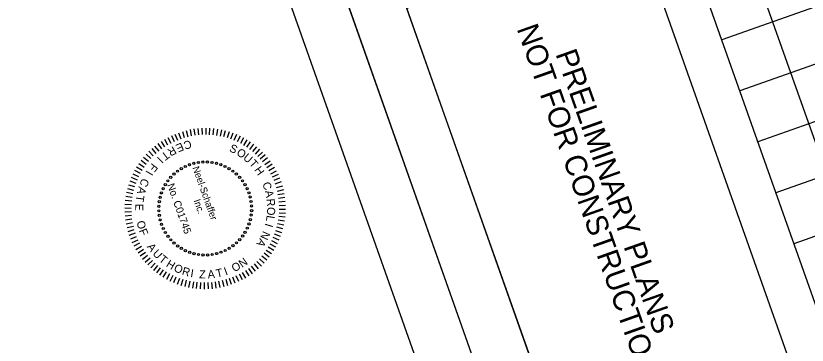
# Model space of a CAD drawing. Extents: x 2002686 to 2004357, y 1138437 to 1140501.
# Drawn here: x 2002880 to 2003246.2, y 1139042.8 to 1139195.1 of the extents above; entities that cross this region are included whole.
import ezdxf

# ---------------------------------------------------------------- set-up
doc = ezdxf.new("R2010")
doc.units = 0
for name, color, linetype in [('RD_SHT_Bndy', 7, 'Continuous'), ('RD_SHT_IplotShp', 7, 'Continuous'), ('RD_SHT_Misc1', 7, 'Continuous'), ('RD_SHT_MjGrid', 7, 'Continuous'), ('RD_SHT_MnGrid', 7, 'Continuous'), ('RD_SHT_TX', 7, 'Continuous')]:
    doc.layers.add(name, color=color, linetype=linetype)

msp = doc.modelspace()

# ---------------------------------------------------------------- linework, layer by layer
at = {"layer": 'RD_SHT_Bndy'}
for p, q in [((2003296.55, 1138457.43), (2002709.57, 1140116.66)), ((2003272.98, 1138449.09), (2002686, 1140108.32)), ((2002760.69, 1140047.13), (2003319.32, 1138468.03))]:
    msp.add_line(p, q, dxfattribs=at)
msp.add_lwpolyline([(2003166.91, 1139236.17), (2003241.95, 1139024.06), (2003135.89, 1138986.54), (2003060.85, 1139198.65)], close=True, dxfattribs=at)
at = {"layer": 'RD_SHT_IplotShp'}
msp.add_lwpolyline([(2003740.39, 1140501.06), (2004340.71, 1138804.11), (2003303.69, 1138437.25), (2002703.37, 1140134.19)], close=True, dxfattribs=at)
at = {"layer": 'RD_SHT_Misc1'}
for p, q in [((2002966.05, 1139143.11), (2002966.18, 1139140.14)), ((2002967.87, 1139143.14), (2002967.85, 1139140.17)), ((2002951.96, 1139139.68), (2002953.22, 1139136.99)), ((2002953.63, 1139140.4), (2002954.75, 1139137.66)), ((2002955.34, 1139141.05), (2002956.32, 1139138.25)), ((2002957.07, 1139141.61), (2002957.92, 1139138.77)), ((2002958.83, 1139142.08), (2002959.54, 1139139.2)), ((2002960.62, 1139142.47), (2002961.18, 1139139.56)), ((2002962.42, 1139142.77), (2002962.84, 1139139.84)), ((2002964.23, 1139142.98), (2002964.5, 1139140.03)), ((2002969.69, 1139143.08), (2002969.53, 1139140.12)), ((2002971.51, 1139142.94), (2002971.2, 1139139.99)), ((2002973.32, 1139142.7), (2002972.87, 1139139.77)), ((2002975.11, 1139142.38), (2002974.52, 1139139.47)), ((2002976.89, 1139141.97), (2002976.16, 1139139.1)), ((2002978.64, 1139141.47), (2002977.77, 1139138.64)), ((2002980.37, 1139140.89), (2002979.36, 1139138.1)), ((2002982.07, 1139140.22), (2002980.92, 1139137.49)), ((2002983.73, 1139139.48), (2002982.45, 1139136.8)), ((2002945.69, 1139135.98), (2002947.44, 1139133.58)), ((2002947.19, 1139137.01), (2002948.82, 1139134.54)), ((2002948.73, 1139137.98), (2002950.25, 1139135.43)), ((2002950.33, 1139138.87), (2002951.71, 1139136.24)), ((2002985.36, 1139138.65), (2002983.95, 1139136.04)), ((2002986.94, 1139137.74), (2002985.4, 1139135.2)), ((2002988.47, 1139136.75), (2002986.81, 1139134.29)), ((2002941.53, 1139132.43), (2002943.61, 1139130.32)), ((2002942.86, 1139133.68), (2002944.84, 1139131.47)), ((2002944.24, 1139134.86), (2002946.11, 1139132.56)), ((2002989.96, 1139135.7), (2002988.18, 1139133.32)), ((2002991.39, 1139134.57), (2002989.5, 1139132.28)), ((2002992.76, 1139133.37), (2002990.76, 1139131.18)), ((2002939.06, 1139129.75), (2002941.34, 1139127.86)), ((2002940.26, 1139131.12), (2002942.45, 1139129.12)), ((2002994.07, 1139132.1), (2002991.97, 1139130.01)), ((2002995.32, 1139130.77), (2002993.12, 1139128.79)), ((2002996.51, 1139129.39), (2002994.21, 1139127.51)), ((2002935.88, 1139125.3), (2002938.42, 1139123.76)), ((2002936.87, 1139126.84), (2002939.32, 1139125.18)), ((2002937.93, 1139128.32), (2002940.3, 1139126.54)), ((2002997.62, 1139127.94), (2002995.23, 1139126.18)), ((2002998.66, 1139126.45), (2002996.19, 1139124.81)), ((2002999.63, 1139124.9), (2002997.08, 1139123.39)), ((2002934.14, 1139122.1), (2002936.81, 1139120.82)), ((2002934.97, 1139123.72), (2002937.58, 1139122.31)), ((2003000.52, 1139123.31), (2002997.9, 1139121.92)), ((2003001.33, 1139121.68), (2002998.65, 1139120.42)), ((2002932.72, 1139118.74), (2002935.5, 1139117.73)), ((2002933.39, 1139120.44), (2002936.12, 1139119.29)), ((2003002.06, 1139120.01), (2002999.32, 1139118.88)), ((2003002.71, 1139118.3), (2002999.91, 1139117.31)), ((2002931.63, 1139115.26), (2002934.51, 1139114.52)), ((2002932.13, 1139117.02), (2002934.97, 1139116.14)), ((2003003.33, 1139116.37), (2003000.48, 1139115.53)), ((2003003.8, 1139114.6), (2003000.91, 1139113.91)), ((2002930.89, 1139111.69), (2002933.83, 1139111.24)), ((2002931.22, 1139113.49), (2002934.13, 1139112.89)), ((2003004.18, 1139112.82), (2003001.26, 1139112.27)), ((2003004.47, 1139111.02), (2003001.53, 1139110.61)), ((2002930.51, 1139108.07), (2002933.47, 1139107.9)), ((2002930.66, 1139109.88), (2002933.61, 1139109.58)), ((2003004.68, 1139109.21), (2003001.72, 1139108.94)), ((2003004.79, 1139107.39), (2003001.83, 1139107.27)), ((2002930.45, 1139106.24), (2002933.42, 1139106.23)), ((2002930.48, 1139104.42), (2002933.45, 1139104.55)), ((2002930.6, 1139102.6), (2002933.56, 1139102.87)), ((2003004.75, 1139103.74), (2003001.79, 1139103.92)), ((2003004.82, 1139105.57), (2003001.85, 1139105.59)), ((2002930.81, 1139100.79), (2002933.75, 1139101.21)), ((2002931.11, 1139098.99), (2002934.02, 1139099.55)), ((2003004.36, 1139100.12), (2003001.43, 1139100.58)), ((2003004.6, 1139101.93), (2003001.65, 1139102.24)), ((2002931.49, 1139097.21), (2002934.38, 1139097.91)), ((2002931.97, 1139095.45), (2002934.81, 1139096.29)), ((2003003.1, 1139094.8), (2003000.27, 1139095.68)), ((2003003.61, 1139096.55), (2003000.74, 1139097.3)), ((2003004.03, 1139098.33), (2003001.12, 1139098.93)), ((2002932.52, 1139093.71), (2002935.32, 1139094.69)), ((2002933.17, 1139092), (2002935.91, 1139093.12)), ((2003001.84, 1139091.38), (2002999.11, 1139092.54)), ((2003002.52, 1139093.07), (2002999.73, 1139094.1)), ((2002933.89, 1139090.33), (2002936.58, 1139091.58)), ((2002934.7, 1139088.7), (2002937.32, 1139090.08)), ((2002935.58, 1139087.1), (2002938.14, 1139088.61)), ((2003000.25, 1139088.1), (2002997.64, 1139089.52)), ((2003001.09, 1139089.72), (2002998.41, 1139091.01)), ((2002936.55, 1139085.55), (2002939.02, 1139087.19)), ((2002937.58, 1139084.05), (2002939.98, 1139085.81)), ((2002997.28, 1139083.51), (2002994.91, 1139085.3)), ((2002998.34, 1139084.99), (2002995.89, 1139086.66)), ((2002999.33, 1139086.52), (2002996.8, 1139088.07)), ((2002938.69, 1139082.61), (2002941, 1139084.47)), ((2002939.87, 1139081.22), (2002942.09, 1139083.19)), ((2002941.12, 1139079.89), (2002943.23, 1139081.97)), ((2002993.67, 1139079.41), (2002991.59, 1139081.52)), ((2002994.94, 1139080.71), (2002992.76, 1139082.73)), ((2002996.14, 1139082.08), (2002993.87, 1139083.98)), ((2002942.43, 1139078.62), (2002944.44, 1139080.8)), ((2002943.8, 1139077.41), (2002945.7, 1139079.69)), ((2002945.23, 1139076.28), (2002947.01, 1139078.65)), ((2002946.71, 1139075.22), (2002948.38, 1139077.67)), ((2002987.99, 1139074.84), (2002986.37, 1139077.32)), ((2002989.49, 1139075.88), (2002987.75, 1139078.27)), ((2002990.94, 1139076.98), (2002989.08, 1139079.29)), ((2002992.34, 1139078.16), (2002990.36, 1139080.38)), ((2002948.24, 1139074.23), (2002949.79, 1139076.76)), ((2002949.82, 1139073.32), (2002951.24, 1139075.92)), ((2002951.44, 1139072.48), (2002952.73, 1139075.16)), ((2002953.1, 1139071.73), (2002954.26, 1139074.46)), ((2002954.8, 1139071.06), (2002955.82, 1139073.84)), ((2002979.83, 1139070.83), (2002978.85, 1139073.63)), ((2002981.54, 1139071.47), (2002980.42, 1139074.22)), ((2002983.21, 1139072.19), (2002981.96, 1139074.88)), ((2002984.85, 1139073), (2002983.47, 1139075.62)), ((2002986.44, 1139073.88), (2002984.94, 1139076.44)), ((2002956.53, 1139070.47), (2002957.41, 1139073.3)), ((2002958.28, 1139069.97), (2002959.02, 1139072.84)), ((2002960.05, 1139069.55), (2002960.65, 1139072.46)), ((2002961.85, 1139069.23), (2002962.3, 1139072.16)), ((2002963.66, 1139068.99), (2002963.97, 1139071.94)), ((2002965.47, 1139068.84), (2002965.64, 1139071.8)), ((2002967.3, 1139068.77), (2002967.32, 1139071.74)), ((2002969.12, 1139068.8), (2002969, 1139071.77)), ((2002970.94, 1139068.92), (2002970.67, 1139071.87)), ((2002972.75, 1139069.13), (2002972.34, 1139072.06)), ((2002974.55, 1139069.42), (2002973.99, 1139072.34)), ((2002976.33, 1139069.8), (2002975.63, 1139072.69)), ((2002978.09, 1139070.27), (2002977.25, 1139073.12))]:
    msp.add_line(p, q, dxfattribs=at)
for centre in [(2002956.55, 1139124.43), (2002958.42, 1139125.42), (2002960.36, 1139126.23), (2002962.38, 1139126.85), (2002964.45, 1139127.26), (2002966.55, 1139127.47), (2002968.66, 1139127.47), (2002970.77, 1139127.26), (2002972.84, 1139126.85), (2002974.85, 1139126.24), (2002976.8, 1139125.43), (2002978.67, 1139124.43), (2002953.17, 1139121.91), (2002954.8, 1139123.25), (2002980.42, 1139123.26), (2002982.05, 1139121.92), (2002949.17, 1139117.03), (2002950.34, 1139118.79), (2002951.68, 1139120.42), (2002983.54, 1139120.43), (2002984.88, 1139118.8), (2002986.05, 1139117.04), (2002948.18, 1139115.17), (2002987.05, 1139115.18), (2002946.77, 1139111.19), (2002947.38, 1139113.22), (2002987.85, 1139113.23), (2002988.44, 1139111.33), (2002946.15, 1139107.02), (2002946.36, 1139109.12), (2002988.86, 1139109.26), (2002989.07, 1139107.16), (2002946.16, 1139104.91), (2002946.37, 1139102.81), (2002988.89, 1139102.95), (2002989.08, 1139105.05), (2002946.78, 1139100.74), (2002947.4, 1139098.73), (2002987.88, 1139098.85), (2002988.48, 1139100.87), (2002948.21, 1139096.78), (2002986.09, 1139095.03), (2002987.08, 1139096.9), (2002949.21, 1139094.92), (2002950.39, 1139093.17), (2002951.73, 1139091.54), (2002983.59, 1139091.64), (2002984.93, 1139093.27), (2002953.23, 1139090.05), (2002954.86, 1139088.71), (2002980.48, 1139088.79), (2002982.11, 1139090.14), (2002956.62, 1139087.55), (2002958.48, 1139086.56), (2002960.44, 1139085.75), (2002962.46, 1139085.15), (2002964.53, 1139084.74), (2002966.63, 1139084.54), (2002968.74, 1139084.55), (2002970.84, 1139084.76), (2002972.91, 1139085.18), (2002974.93, 1139085.8), (2002976.87, 1139086.61), (2002978.73, 1139087.62)]:
    msp.add_circle(centre, 0.513, dxfattribs=at)
at = {"layer": 'RD_SHT_MjGrid'}
for p, q in [((2002885.6, 1140091.32), (2003444.23, 1138512.22)), ((2003607.27, 1139325.66), (2003206.61, 1139183.92))]:
    msp.add_line(p, q, dxfattribs=at)
at = {"layer": 'RD_SHT_MnGrid'}
for p, q in [((2002909.17, 1140099.65), (2003467.8, 1138520.55)), ((2003615.61, 1139302.1), (2003214.94, 1139160.35)), ((2003623.95, 1139278.53), (2003223.28, 1139136.79)), ((2003632.29, 1139254.96), (2003231.62, 1139113.22)), ((2003640.63, 1139231.39), (2003239.96, 1139089.65))]:
    msp.add_line(p, q, dxfattribs=at)

# ---------------------------------------------------------------- texts
at = {"layer": 'RD_SHT_Misc1'}
for s, height, rotation, p in [('E', 3.72, 202.976, (2002956.7, 1139136.56)), ('C', 3.72, 195.5931, (2002960.71, 1139137.72)), ('R', 3.72, 210.3589, (2002952.87, 1139134.91)), ('S', 3.72, 334.1871, (2002978.45, 1139132.64)), ('O', 3.72, 326.8042, (2002981.78, 1139131.03)), ('I', 3.72, 225.1247, (2002946, 1139130.19)), ('T', 3.72, 217.7418, (2002949.28, 1139132.77)), ('U', 3.72, 319.4213, (2002984.87, 1139129)), ('T', 3.72, 312.0384, (2002987.68, 1139126.6)), ('F', 3.72, 232.5077, (2002943.08, 1139127.21)), ('Neel-Schaffer ', 3.1803, 289.482, (2002961.71, 1139124.85)), ('H', 3.72, 304.6555, (2002990.15, 1139123.85)), ('I', 3.72, 239.8906, (2002940.56, 1139123.88)), ('C', 3.72, 247.2735, (2002938.49, 1139120.25)), ('No. C01745', 3.421, 289.482, (2002949.98, 1139116.93)), ('C', 3.72, 289.831, (2002993.96, 1139117.5)), ('A', 3.72, 254.6564, (2002936.91, 1139116.39)), ('A', 3.72, 282.4481, (2002995.21, 1139114.02)), ('T', 3.72, 262.0393, (2002935.83, 1139112.35)), ('Inc.', 3.18, 289.482, (2002962.21, 1139109.68)), ('R', 3.72, 275.0652, (2002996.01, 1139110.41)), ('E', 3.72, 269.4223, (2002935.29, 1139108.21)), ('O', 3.72, 267.6823, (2002996.34, 1139106.73)), ('O', 3.72, 284.2467, (2002935.81, 1139099.86)), ('L', 3.72, 260.2993, (2002996.19, 1139103.03)), ('F', 3.72, 291.6296, (2002936.86, 1139095.82)), ('I', 3.72, 252.9164, (2002995.56, 1139099.39)), ('A', 3.72, 238.1506, (2002992.95, 1139092.49)), ('N', 3.72, 245.5335, (2002994.48, 1139095.86)), ('A', 3.72, 306.454, (2002940.5, 1139088.29)), ('U', 3.72, 313.837, (2002943.01, 1139084.95)), ('T', 3.72, 321.2199, (2002945.92, 1139081.96)), ('H', 3.72, 328.6028, (2002949.2, 1139079.37)), ('O', 3.72, 27.6662, (2002981.03, 1139076.51)), ('N', 3.72, 35.0491, (2002984.71, 1139078.48)), ('O', 3.72, 335.9857, (2002952.78, 1139077.22)), ('R', 3.72, 343.3686, (2002956.6, 1139075.55)), ('I', 3.72, 350.7516, (2002960.61, 1139074.39)), ('Z', 3.72, 358.1345, (2002964.74, 1139073.75)), ('A', 3.72, 5.5174, (2002968.91, 1139073.64)), ('T', 3.72, 12.9003, (2002973.06, 1139074.08)), ('I', 3.72, 20.2832, (2002977.13, 1139075.04))]:
    msp.add_text(s, height=height, rotation=rotation, dxfattribs=at).set_placement(p)
at = {"layer": 'RD_SHT_TX'}
for s, p in [('NOT FOR CONSTRUCTION', (2003111.67, 1139189.15)), ('PRELIMINARY PLANS', (2003129.6, 1139177.51))]:
    msp.add_text(s, height=10, rotation=289.482, dxfattribs=at).set_placement(p)

doc.saveas('drawing.dxf')
